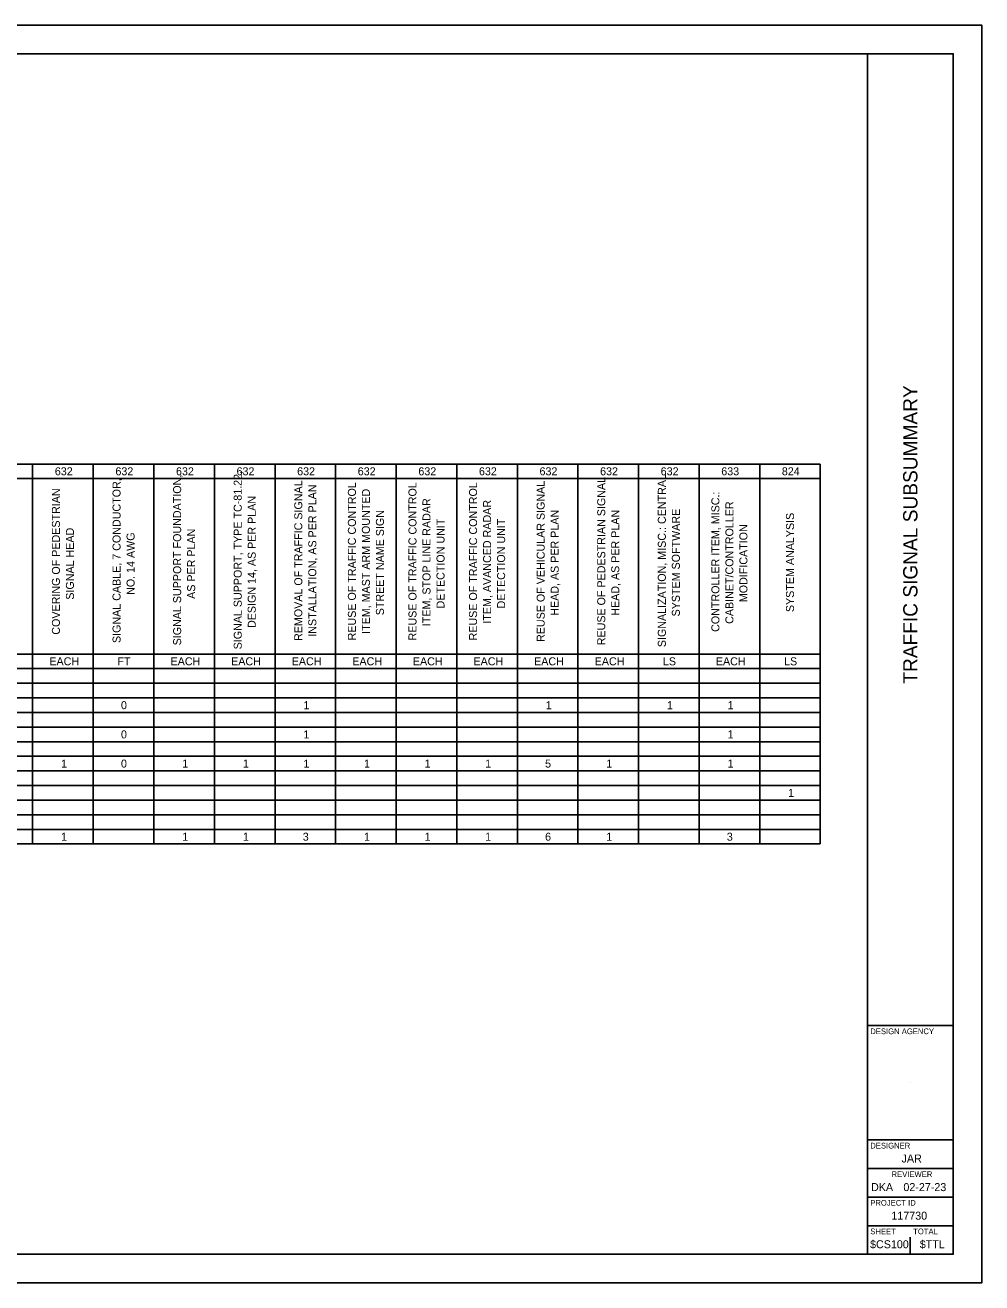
# Model space of a CAD drawing. Extents: x 0 to 34, y 0 to 22.
# Drawn here: x 17.28 to 34, y 0 to 22 of the extents above; entities that cross this region are included whole.
import ezdxf

# ---------------------------------------------------------------- set-up
doc = ezdxf.new("R2010")
doc.units = 0
for name, color, linetype in [('SH_Border', 7, 'Continuous'), ('SH_Cut_Line', 7, 'Continuous'), ('SH_Data', 7, 'Continuous'), ('SH_Text', 7, 'Continuous')]:
    doc.layers.add(name, color=color, linetype=linetype)

msp = doc.modelspace()

# ---------------------------------------------------------------- linework, layer by layer
at = {"layer": 'SH_Border'}
for p, q in [((32, 0.5), (32, 21.5)), ((32, 4.5), (33.5, 4.5)), ((32, 2.5), (33.5, 2.5)), ((32, 2), (33.5, 2)), ((32, 1.5), (33.5, 1.5)), ((32, 1), (33.5, 1))]:
    msp.add_line(p, q, dxfattribs=at)
msp.add_lwpolyline([(1.5, 21.5), (33.5, 21.5), (33.5, 0.5), (1.5, 0.5)], close=True, dxfattribs=at)
at = {"layer": 'SH_Cut_Line'}
msp.add_lwpolyline([(0, 0), (34, 0), (34, 22), (0, 22)], close=True, dxfattribs=at)
at = {"layer": 'SH_Data'}
for p, q in [((32.75, 3.5), (32.75, 3.5)), ((32.375, 0.675), (32.375, 0.675)), ((32.75, 0.5), (32.75, 0.8))]:
    msp.add_line(p, q, dxfattribs=at)
at = {"layer": 'SH_Text'}
for p, q in [((15.289, 14.323), (26.94, 14.323)), ((17.407, 14.323), (17.407, 14.068)), ((18.467, 14.323), (18.467, 14.068)), ((19.526, 14.323), (19.526, 14.068)), ((20.585, 14.323), (20.585, 14.068)), ((21.644, 14.323), (21.644, 14.068)), ((22.703, 14.323), (22.703, 14.068)), ((23.762, 14.323), (23.762, 14.068)), ((24.821, 14.323), (24.821, 14.068)), ((25.88, 14.323), (25.88, 14.068)), ((26.94, 14.323), (27.999, 14.323)), ((26.94, 14.323), (26.94, 14.068)), ((27.999, 14.323), (30.117, 14.323)), ((27.999, 14.323), (27.999, 14.068)), ((29.058, 14.323), (29.058, 14.068)), ((30.117, 14.323), (31.176, 14.323)), ((30.117, 14.323), (30.117, 14.068)), ((31.176, 14.323), (31.176, 14.068)), ((15.289, 14.068), (26.94, 14.068)), ((17.407, 14.068), (17.407, 13.812)), ((18.467, 14.068), (18.467, 13.812)), ((19.526, 14.068), (19.526, 13.812)), ((20.585, 14.068), (20.585, 13.812)), ((21.644, 14.068), (21.644, 13.812)), ((22.703, 14.068), (22.703, 13.812)), ((23.762, 14.068), (23.762, 13.812)), ((24.821, 14.068), (24.821, 13.812)), ((25.88, 14.068), (25.88, 13.812)), ((26.94, 14.068), (27.999, 14.068)), ((26.94, 14.068), (26.94, 13.812)), ((27.999, 14.068), (30.117, 14.068)), ((27.999, 14.068), (27.999, 13.812)), ((29.058, 14.068), (29.058, 13.812)), ((30.117, 14.068), (31.176, 14.068)), ((30.117, 14.068), (30.117, 13.812)), ((31.176, 14.068), (31.176, 13.812)), ((17.407, 13.812), (17.407, 13.557)), ((18.467, 13.812), (18.467, 13.557)), ((19.526, 13.812), (19.526, 13.557)), ((20.585, 13.812), (20.585, 13.557)), ((21.644, 13.812), (21.644, 13.557)), ((22.703, 13.812), (22.703, 13.557)), ((23.762, 13.812), (23.762, 13.557)), ((24.821, 13.812), (24.821, 13.557)), ((25.88, 13.812), (25.88, 13.557)), ((26.94, 13.812), (26.94, 13.557)), ((27.999, 13.812), (27.999, 13.557)), ((29.058, 13.812), (29.058, 13.557)), ((30.117, 13.812), (30.117, 13.557)), ((31.176, 13.812), (31.176, 13.557)), ((17.407, 13.557), (17.407, 13.301)), ((18.467, 13.557), (18.467, 13.301)), ((19.526, 13.557), (19.526, 13.301)), ((20.585, 13.557), (20.585, 13.301)), ((21.644, 13.557), (21.644, 13.301)), ((22.703, 13.557), (22.703, 13.301)), ((23.762, 13.557), (23.762, 13.301)), ((24.821, 13.557), (24.821, 13.301)), ((25.88, 13.557), (25.88, 13.301)), ((26.94, 13.557), (26.94, 13.301)), ((27.999, 13.557), (27.999, 13.301)), ((29.058, 13.557), (29.058, 13.301)), ((30.117, 13.557), (30.117, 13.301)), ((31.176, 13.557), (31.176, 13.301)), ((17.407, 13.301), (17.407, 13.045)), ((18.467, 13.301), (18.467, 13.045)), ((19.526, 13.301), (19.526, 13.045)), ((20.585, 13.301), (20.585, 13.045)), ((21.644, 13.301), (21.644, 13.045)), ((22.703, 13.301), (22.703, 13.045)), ((23.762, 13.301), (23.762, 13.045)), ((24.821, 13.301), (24.821, 13.045)), ((25.88, 13.301), (25.88, 13.045)), ((26.94, 13.301), (26.94, 13.045)), ((27.999, 13.301), (27.999, 13.045)), ((29.058, 13.301), (29.058, 13.045)), ((30.117, 13.301), (30.117, 13.045)), ((31.176, 13.301), (31.176, 13.045)), ((17.407, 13.045), (17.407, 12.79)), ((18.467, 13.045), (18.467, 12.79)), ((19.526, 13.045), (19.526, 12.79)), ((20.585, 13.045), (20.585, 12.79)), ((21.644, 13.045), (21.644, 12.79)), ((22.703, 13.045), (22.703, 12.79)), ((23.762, 13.045), (23.762, 12.79)), ((24.821, 13.045), (24.821, 12.79)), ((25.88, 13.045), (25.88, 12.79)), ((26.94, 13.045), (26.94, 12.79)), ((27.999, 13.045), (27.999, 12.79)), ((29.058, 13.045), (29.058, 12.79)), ((30.117, 13.045), (30.117, 12.79)), ((31.176, 13.045), (31.176, 12.79)), ((17.407, 12.79), (17.407, 12.023)), ((18.467, 12.79), (18.467, 12.023)), ((19.526, 12.79), (19.526, 12.023)), ((20.585, 12.79), (20.585, 12.023)), ((21.644, 12.79), (21.644, 12.023)), ((22.703, 12.79), (22.703, 12.023)), ((23.762, 12.79), (23.762, 12.023)), ((24.821, 12.79), (24.821, 12.023)), ((25.88, 12.79), (25.88, 12.023)), ((26.94, 12.79), (26.94, 12.023)), ((27.999, 12.79), (27.999, 12.023)), ((29.058, 12.79), (29.058, 12.023)), ((30.117, 12.79), (30.117, 12.023)), ((31.176, 12.79), (31.176, 12.023)), ((17.407, 12.023), (17.407, 11.256)), ((18.467, 12.023), (18.467, 11.256)), ((19.526, 12.023), (19.526, 11.256)), ((20.585, 12.023), (20.585, 11.256)), ((21.644, 12.023), (21.644, 11.256)), ((22.703, 12.023), (22.703, 11.256)), ((23.762, 12.023), (23.762, 11.256)), ((24.821, 12.023), (24.821, 11.256)), ((25.88, 12.023), (25.88, 11.256)), ((26.94, 12.023), (26.94, 11.256)), ((27.999, 12.023), (27.999, 11.256)), ((29.058, 12.023), (29.058, 11.256)), ((30.117, 12.023), (30.117, 11.256)), ((31.176, 12.023), (31.176, 11.256)), ((17.407, 11.256), (17.407, 11)), ((18.467, 11.256), (18.467, 11)), ((19.526, 11.256), (19.526, 11)), ((20.585, 11.256), (20.585, 11)), ((21.644, 11.256), (21.644, 11)), ((22.703, 11.256), (22.703, 11)), ((23.762, 11.256), (23.762, 11)), ((24.821, 11.256), (24.821, 11)), ((25.88, 11.256), (25.88, 11)), ((26.94, 11.256), (26.94, 11)), ((27.999, 11.256), (27.999, 11)), ((29.058, 11.256), (29.058, 11)), ((30.117, 11.256), (30.117, 11)), ((31.176, 11.256), (31.176, 11)), ((15.289, 11), (26.94, 11)), ((17.407, 11), (17.407, 10.744)), ((18.467, 11), (18.467, 10.744)), ((19.526, 11), (19.526, 10.744)), ((20.585, 11), (20.585, 10.744)), ((21.644, 11), (21.644, 10.744)), ((22.703, 11), (22.703, 10.744)), ((23.762, 11), (23.762, 10.744)), ((24.821, 11), (24.821, 10.744)), ((25.88, 11), (25.88, 10.744)), ((26.94, 11), (27.999, 11)), ((26.94, 11), (26.94, 10.744)), ((27.999, 11), (30.117, 11)), ((27.999, 11), (27.999, 10.744)), ((29.058, 11), (29.058, 10.744)), ((30.117, 11), (31.176, 11)), ((30.117, 11), (30.117, 10.744)), ((31.176, 11), (31.176, 10.744)), ((15.289, 10.744), (26.94, 10.744)), ((17.407, 10.744), (17.407, 10.489)), ((18.467, 10.744), (18.467, 10.489)), ((19.526, 10.744), (19.526, 10.489)), ((20.585, 10.744), (20.585, 10.489)), ((21.644, 10.744), (21.644, 10.489)), ((22.703, 10.744), (22.703, 10.489)), ((23.762, 10.744), (23.762, 10.489)), ((24.821, 10.744), (24.821, 10.489)), ((25.88, 10.744), (25.88, 10.489)), ((26.94, 10.744), (27.999, 10.744)), ((26.94, 10.744), (26.94, 10.489)), ((27.999, 10.744), (30.117, 10.744)), ((27.999, 10.744), (27.999, 10.489)), ((29.058, 10.744), (29.058, 10.489)), ((30.117, 10.744), (31.176, 10.744)), ((30.117, 10.744), (30.117, 10.489)), ((31.176, 10.744), (31.176, 10.489)), ((15.289, 10.489), (26.94, 10.489)), ((17.407, 10.489), (17.407, 10.233)), ((18.467, 10.489), (18.467, 10.233)), ((19.526, 10.489), (19.526, 10.233)), ((20.585, 10.489), (20.585, 10.233)), ((21.644, 10.489), (21.644, 10.233)), ((22.703, 10.489), (22.703, 10.233)), ((23.762, 10.489), (23.762, 10.233)), ((24.821, 10.489), (24.821, 10.233)), ((25.88, 10.489), (25.88, 10.233)), ((26.94, 10.489), (27.999, 10.489)), ((26.94, 10.489), (26.94, 10.233)), ((27.999, 10.489), (30.117, 10.489)), ((27.999, 10.489), (27.999, 10.233)), ((29.058, 10.489), (29.058, 10.233)), ((30.117, 10.489), (31.176, 10.489)), ((30.117, 10.489), (30.117, 10.233)), ((31.176, 10.489), (31.176, 10.233)), ((15.289, 10.233), (26.94, 10.233)), ((17.407, 10.233), (17.407, 9.977)), ((18.467, 10.233), (18.467, 9.977)), ((19.526, 10.233), (19.526, 9.977)), ((20.585, 10.233), (20.585, 9.977)), ((21.644, 10.233), (21.644, 9.977)), ((22.703, 10.233), (22.703, 9.977)), ((23.762, 10.233), (23.762, 9.977)), ((24.821, 10.233), (24.821, 9.977)), ((25.88, 10.233), (25.88, 9.977)), ((26.94, 10.233), (27.999, 10.233)), ((26.94, 10.233), (26.94, 9.977)), ((27.999, 10.233), (30.117, 10.233)), ((27.999, 10.233), (27.999, 9.977)), ((29.058, 10.233), (29.058, 9.977)), ((30.117, 10.233), (31.176, 10.233)), ((30.117, 10.233), (30.117, 9.977)), ((31.176, 10.233), (31.176, 9.977)), ((15.289, 9.977), (26.94, 9.977)), ((17.407, 9.977), (17.407, 9.722)), ((18.467, 9.977), (18.467, 9.722)), ((19.526, 9.977), (19.526, 9.722)), ((20.585, 9.977), (20.585, 9.722)), ((21.644, 9.977), (21.644, 9.722)), ((22.703, 9.977), (22.703, 9.722)), ((23.762, 9.977), (23.762, 9.722)), ((24.821, 9.977), (24.821, 9.722)), ((25.88, 9.977), (25.88, 9.722)), ((26.94, 9.977), (27.999, 9.977)), ((26.94, 9.977), (26.94, 9.722)), ((27.999, 9.977), (30.117, 9.977)), ((27.999, 9.977), (27.999, 9.722)), ((29.058, 9.977), (29.058, 9.722)), ((30.117, 9.977), (31.176, 9.977)), ((30.117, 9.977), (30.117, 9.722)), ((31.176, 9.977), (31.176, 9.722)), ((15.289, 9.722), (26.94, 9.722)), ((17.407, 9.722), (17.407, 9.466)), ((18.467, 9.722), (18.467, 9.466)), ((19.526, 9.722), (19.526, 9.466)), ((20.585, 9.722), (20.585, 9.466)), ((21.644, 9.722), (21.644, 9.466)), ((22.703, 9.722), (22.703, 9.466)), ((23.762, 9.722), (23.762, 9.466)), ((24.821, 9.722), (24.821, 9.466)), ((25.88, 9.722), (25.88, 9.466)), ((26.94, 9.722), (27.999, 9.722)), ((26.94, 9.722), (26.94, 9.466)), ((27.999, 9.722), (30.117, 9.722)), ((27.999, 9.722), (27.999, 9.466)), ((29.058, 9.722), (29.058, 9.466)), ((30.117, 9.722), (31.176, 9.722)), ((30.117, 9.722), (30.117, 9.466)), ((31.176, 9.722), (31.176, 9.466)), ((15.289, 9.466), (26.94, 9.466)), ((17.407, 9.466), (17.407, 9.21)), ((18.467, 9.466), (18.467, 9.21)), ((19.526, 9.466), (19.526, 9.21)), ((20.585, 9.466), (20.585, 9.21)), ((21.644, 9.466), (21.644, 9.21)), ((22.703, 9.466), (22.703, 9.21)), ((23.762, 9.466), (23.762, 9.21)), ((24.821, 9.466), (24.821, 9.21)), ((25.88, 9.466), (25.88, 9.21)), ((26.94, 9.466), (27.999, 9.466)), ((26.94, 9.466), (26.94, 9.21)), ((27.999, 9.466), (30.117, 9.466)), ((27.999, 9.466), (27.999, 9.21)), ((29.058, 9.466), (29.058, 9.21)), ((30.117, 9.466), (31.176, 9.466)), ((30.117, 9.466), (30.117, 9.21)), ((31.176, 9.466), (31.176, 9.21)), ((15.289, 9.21), (26.94, 9.21)), ((17.407, 9.21), (17.407, 8.955)), ((18.467, 9.21), (18.467, 8.955)), ((19.526, 9.21), (19.526, 8.955)), ((20.585, 9.21), (20.585, 8.955)), ((21.644, 9.21), (21.644, 8.955)), ((22.703, 9.21), (22.703, 8.955)), ((23.762, 9.21), (23.762, 8.955)), ((24.821, 9.21), (24.821, 8.955)), ((25.88, 9.21), (25.88, 8.955)), ((26.94, 9.21), (27.999, 9.21)), ((26.94, 9.21), (26.94, 8.955)), ((27.999, 9.21), (30.117, 9.21)), ((27.999, 9.21), (27.999, 8.955)), ((29.058, 9.21), (29.058, 8.955)), ((30.117, 9.21), (31.176, 9.21)), ((30.117, 9.21), (30.117, 8.955)), ((31.176, 9.21), (31.176, 8.955)), ((15.289, 8.955), (26.94, 8.955)), ((17.407, 8.955), (17.407, 8.699)), ((18.467, 8.955), (18.467, 8.699)), ((19.526, 8.955), (19.526, 8.699)), ((20.585, 8.955), (20.585, 8.699)), ((21.644, 8.955), (21.644, 8.699)), ((22.703, 8.955), (22.703, 8.699)), ((23.762, 8.955), (23.762, 8.699)), ((24.821, 8.955), (24.821, 8.699)), ((25.88, 8.955), (25.88, 8.699)), ((26.94, 8.955), (27.999, 8.955)), ((26.94, 8.955), (26.94, 8.699)), ((27.999, 8.955), (30.117, 8.955)), ((27.999, 8.955), (27.999, 8.699)), ((29.058, 8.955), (29.058, 8.699)), ((30.117, 8.955), (31.176, 8.955)), ((30.117, 8.955), (30.117, 8.699)), ((31.176, 8.955), (31.176, 8.699)), ((15.289, 8.699), (26.94, 8.699)), ((17.407, 8.699), (17.407, 8.443)), ((18.467, 8.699), (18.467, 8.443)), ((19.526, 8.699), (19.526, 8.443)), ((20.585, 8.699), (20.585, 8.443)), ((21.644, 8.699), (21.644, 8.443)), ((22.703, 8.699), (22.703, 8.443)), ((23.762, 8.699), (23.762, 8.443)), ((24.821, 8.699), (24.821, 8.443)), ((25.88, 8.699), (25.88, 8.443)), ((26.94, 8.699), (27.999, 8.699)), ((26.94, 8.699), (26.94, 8.443)), ((27.999, 8.699), (30.117, 8.699)), ((27.999, 8.699), (27.999, 8.443)), ((29.058, 8.699), (29.058, 8.443)), ((30.117, 8.699), (31.176, 8.699)), ((30.117, 8.699), (30.117, 8.443)), ((31.176, 8.699), (31.176, 8.443)), ((15.289, 8.443), (26.94, 8.443)), ((17.407, 8.443), (17.407, 8.188)), ((18.467, 8.443), (18.467, 8.188)), ((19.526, 8.443), (19.526, 8.188)), ((20.585, 8.443), (20.585, 8.188)), ((21.644, 8.443), (21.644, 8.188)), ((22.703, 8.443), (22.703, 8.188)), ((23.762, 8.443), (23.762, 8.188)), ((24.821, 8.443), (24.821, 8.188)), ((25.88, 8.443), (25.88, 8.188)), ((26.94, 8.443), (27.999, 8.443)), ((26.94, 8.443), (26.94, 8.188)), ((27.999, 8.443), (30.117, 8.443)), ((27.999, 8.443), (27.999, 8.188)), ((29.058, 8.443), (29.058, 8.188)), ((30.117, 8.443), (31.176, 8.443)), ((30.117, 8.443), (30.117, 8.188)), ((31.176, 8.443), (31.176, 8.188)), ((15.289, 8.188), (26.94, 8.188)), ((17.407, 8.188), (17.407, 7.932)), ((18.467, 8.188), (18.467, 7.932)), ((19.526, 8.188), (19.526, 7.932)), ((20.585, 8.188), (20.585, 7.932)), ((21.644, 8.188), (21.644, 7.932)), ((22.703, 8.188), (22.703, 7.932)), ((23.762, 8.188), (23.762, 7.932)), ((24.821, 8.188), (24.821, 7.932)), ((25.88, 8.188), (25.88, 7.932)), ((26.94, 8.188), (27.999, 8.188)), ((26.94, 8.188), (26.94, 7.932)), ((27.999, 8.188), (30.117, 8.188)), ((27.999, 8.188), (27.999, 7.932)), ((29.058, 8.188), (29.058, 7.932)), ((30.117, 8.188), (31.176, 8.188)), ((30.117, 8.188), (30.117, 7.932)), ((31.176, 8.188), (31.176, 7.932)), ((15.289, 7.932), (26.94, 7.932)), ((17.407, 7.932), (17.407, 7.677)), ((18.467, 7.932), (18.467, 7.677)), ((19.526, 7.932), (19.526, 7.677)), ((20.585, 7.932), (20.585, 7.677)), ((21.644, 7.932), (21.644, 7.677)), ((22.703, 7.932), (22.703, 7.677)), ((23.762, 7.932), (23.762, 7.677)), ((24.821, 7.932), (24.821, 7.677)), ((25.88, 7.932), (25.88, 7.677)), ((26.94, 7.932), (27.999, 7.932)), ((26.94, 7.932), (26.94, 7.677)), ((27.999, 7.932), (30.117, 7.932)), ((27.999, 7.932), (27.999, 7.677)), ((29.058, 7.932), (29.058, 7.677)), ((30.117, 7.932), (31.176, 7.932)), ((30.117, 7.932), (30.117, 7.677)), ((31.176, 7.932), (31.176, 7.677)), ((15.289, 7.677), (26.94, 7.677)), ((26.94, 7.677), (27.999, 7.677)), ((27.999, 7.677), (30.117, 7.677)), ((30.117, 7.677), (31.176, 7.677))]:
    msp.add_line(p, q, dxfattribs=at)

# ---------------------------------------------------------------- texts
at = {"layer": 'SH_Data'}
msp.add_text('TRAFFIC SIGNAL SUBSUMMARY', height=0.25, rotation=90, dxfattribs=at).set_placement((32.875, 10.481))
for s, height, p in [('DESIGN AGENCY', 0.1, (32.05, 4.35)), ('DESIGNER', 0.1, (32.05, 2.35)), ('JAR', 0.14, (32.597, 2.105)), ('REVIEWER', 0.1, (32.422, 1.85)), ('DKA', 0.14, (32.063, 1.605)), ('02-27-23', 0.14, (32.629, 1.605)), ('PROJECT ID', 0.1, (32.05, 1.35)), ('117730', 0.14, (32.419, 1.105)), ('SHEET', 0.1, (32.05, 0.85)), ('TOTAL', 0.1, (32.8, 0.85)), ('$CS100', 0.14, (32.046, 0.605)), ('$TTL', 0.14, (32.915, 0.605))]:
    msp.add_text(s, height=height, dxfattribs=at).set_placement(p)
at = {"layer": 'SH_Text'}
for s, p in [('632', (17.795, 14.126)), ('632', (18.854, 14.126)), ('632', (19.913, 14.126)), ('632', (20.972, 14.126)), ('632', (22.031, 14.126)), ('632', (23.09, 14.126)), ('632', (24.15, 14.126)), ('632', (25.209, 14.126)), ('632', (26.268, 14.126)), ('632', (27.327, 14.126)), ('632', (28.386, 14.126)), ('633', (29.445, 14.126)), ('824', (30.504, 14.126)), ('EACH', (17.699, 10.802)), ('FT', (18.89, 10.802)), ('EACH', (19.818, 10.802)), ('EACH', (20.877, 10.802)), ('EACH', (21.936, 10.802)), ('EACH', (22.995, 10.802)), ('EACH', (24.054, 10.802)), ('EACH', (25.113, 10.802)), ('EACH', (26.173, 10.802)), ('EACH', (27.232, 10.802)), ('LS', (28.425, 10.802)), ('EACH', (29.35, 10.802)), ('LS', (30.543, 10.802)), ('0', (18.951, 10.035)), ('1', (22.141, 10.035)), ('1', (26.377, 10.035)), ('1', (28.496, 10.035)), ('1', (29.555, 10.035)), ('0', (18.951, 9.524)), ('1', (22.141, 9.524)), ('1', (29.555, 9.524)), ('1', (17.904, 9.013)), ('0', (18.951, 9.013)), ('1', (20.022, 9.013)), ('1', (21.082, 9.013)), ('1', (22.141, 9.013)), ('1', (23.2, 9.013)), ('1', (24.259, 9.013)), ('1', (25.318, 9.013)), ('5', (26.365, 9.013)), ('1', (27.436, 9.013)), ('1', (29.555, 9.013)), ('1', (30.614, 8.501)), ('1', (17.904, 7.734)), ('1', (20.022, 7.734)), ('1', (21.082, 7.734)), ('3', (22.129, 7.734)), ('1', (23.2, 7.734)), ('1', (24.259, 7.734)), ('1', (25.318, 7.734)), ('6', (26.365, 7.734)), ('1', (27.436, 7.734)), ('3', (29.542, 7.734))]:
    msp.add_text(s, height=0.14, dxfattribs=at).set_placement(p)
for s, p in [('SIGNAL SUPPORT FOUNDATION, ', (20.003, 11.151)), ('SIGNAL SUPPORT, TYPE TC-81.22, ', (21.062, 11.081)), ('REUSE OF PEDESTRIAN SIGNAL ', (27.417, 11.153)), ('SIGNALIZATION, MISC.: CENTRAL ', (28.476, 11.12)), ('COVERING OF PEDESTRIAN ', (17.884, 11.338)), ('SIGNAL CABLE, 7 CONDUCTOR, ', (18.944, 11.192)), ('REMOVAL OF TRAFFIC SIGNAL ', (22.121, 11.228)), ('INSTALLATION, AS PER PLAN', (22.366, 11.302)), ('REUSE OF TRAFFIC CONTROL ', (23.058, 11.238)), ('ITEM, MAST ARM MOUNTED ', (23.303, 11.352)), ('REUSE OF TRAFFIC CONTROL ', (24.117, 11.238)), ('REUSE OF TRAFFIC CONTROL ', (25.176, 11.238)), ('REUSE OF VEHICULAR SIGNAL ', (26.358, 11.211)), ('DESIGN 14, AS PER PLAN', (21.307, 11.455)), ('ITEM, STOP LINE RADAR ', (24.362, 11.487)), ('ITEM, AVANCED RADAR ', (25.421, 11.531)), ('CONTROLLER ITEM, MISC.: ', (29.412, 11.387)), ('CABINET/CONTROLLER ', (29.657, 11.527)), ('STREET NAME SIGN', (23.548, 11.677)), ('HEAD, AS PER PLAN', (26.603, 11.67)), ('HEAD, AS PER PLAN', (27.662, 11.67)), ('SYSTEM SOFTWARE', (28.721, 11.657)), ('SYSTEM ANALYSIS', (30.717, 11.733)), ('DETECTION UNIT', (24.607, 11.797)), ('DETECTION UNIT', (25.666, 11.797)), ('MODIFICATION', (29.902, 11.907)), ('SIGNAL HEAD', (18.129, 11.95)), ('NO. 14 AWG', (19.189, 12.034)), ('AS PER PLAN', (20.248, 11.964))]:
    msp.add_text(s, height=0.14, rotation=90, dxfattribs=at).set_placement(p)

doc.saveas('drawing.dxf')
